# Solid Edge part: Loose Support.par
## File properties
Author: davee
Template: Normal.par
Last saved by: davee
Revision: 8
Application: Solid Edge
Accuracy: 0.990
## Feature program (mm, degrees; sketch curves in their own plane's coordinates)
body "unnamed Body 1"
sketch for "unnamed Cutout 1" plane through (0, -40, -2.125) normal (0, -1, 0) x-axis (1, 0, 0)
  line (-6.001, 8.125) -> (6.001, 8.125)
extrude "unnamed Cutout 1" cut finite 158.75 along -normal
delete faces "unnamed DeleteFaces 1"
fillet "Round_2" radius 1
sketch for "ExtrudedCutout_2" plane through (0, 5.25, -10) normal (0, 0, -1) x-axis (0, -1, 0)
extrude "ExtrudedCutout_2" cut finite 31.75 along -normal
sketch for "ExtrudedCutout_3" plane through (0, 5.25, -10) normal (0, 0, -1) x-axis (0, -1, 0)
extrude "ExtrudedCutout_3" cut finite 79.375 along -normal
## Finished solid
Body 1: solid body, 119 faces, 270 edges, 158 vertices.
  Faces by surface: plane 45, cylinder 24, torus 20, cone 14, spline 6, swept 6, spun 4
  Edges by curve: line 146, circle 80, curve on surface 18, spline 18, intersection 8
Bounding box of the edges (mm; curved faces can reach further): 38.000 x 90.500 x 16.000, from (-19, -40, -10) to (19, 50.5, 6).
Cylindrical faces by radius (mm): R0.75 x4, R0.8 x6, R1 x9, R1.5 x2, R3 x3
Conical faces (half-angle, radius in mm at the cone's reference point): 1 deg R1.75 x2, 1 deg R2.4 x2, 3 deg R1.5 x8, 3 deg R3.7722 x1, 3 deg R3.7827 x1
Toroidal faces (ring radius, tube radius in mm): R0.5 r1 x2, R0.75 r0.75 x2, R2 r1 x2, R2.25 r0.75 x2, R2.2592 r0.8 x8, R3.013 r0.8 x1, R3.0235 r0.8 x1, R5.3762 r1 x1, R5.3868 r1 x1
Planar faces by outward normal: +x 4, +y 7, +z 1, -x 5, -y 6, -z 10, oblique 12
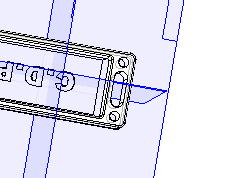
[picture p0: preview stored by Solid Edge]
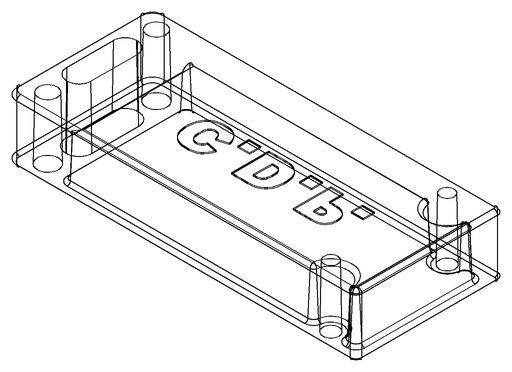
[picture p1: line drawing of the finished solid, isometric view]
